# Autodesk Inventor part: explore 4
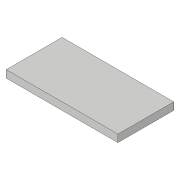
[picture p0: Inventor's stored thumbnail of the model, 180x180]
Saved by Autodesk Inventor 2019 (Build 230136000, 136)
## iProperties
Created: 2020-02
Part Number: explore 4
Material: Generic
Document SubType Name: Modeling
Designer: Naveen G
Density: 1 g/cm^3
Appearance: Default
Author: Naveen G
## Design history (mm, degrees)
sketch "Sketch1"
  geometry: L1 (0, 0)-(300, 0); L2 (300, 0)-(300, 150); L3 (300, 150)-(-300, 150); L4 (-300, 150)-(-300, -150); L5 (-300, -150)-(300, -150); L6 (300, -150)-(300, 0)
  constraints: 12 end point, 4 perpendicular, 1 horizontal, 1 point on line
  dimensions: "d0" = 300 distance of L1.start L1.end; "d1" = 150 distance of L1.end L2.end; "d2" = 600 distance of L2.end L3.end; "d3" = 300 distance of L3.end L4.end; "d4" = 600 distance of L4.end L5.end
extrude "Extrusion1" new body sketch "Sketch1" distance "d5" = 40; taper "d6" = 0 deg
body "Solid1"
